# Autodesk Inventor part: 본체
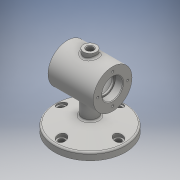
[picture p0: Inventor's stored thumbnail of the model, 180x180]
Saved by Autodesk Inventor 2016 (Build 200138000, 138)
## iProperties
Created: 2018-12
Part Number: 본체
Material: 일반
Document SubType Name: Modeling
Designer: 605-17
Density: 1 g/cm^3
Appearance: 기본값
Author: 605-17
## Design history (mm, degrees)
sketch "스케치1"
  geometry: C1 r 55 at (0, 0); 1 further point
  constraints: 1 centre point, 1 coincident
  dimensions: "d0" = 110 diameter of C1
extrude "돌출1" new body sketch "스케치1" distance "d1" = 11; taper "d2" = 0 deg
sketch "스케치2"
  geometry: L1 (0, 11)-(0, 22.522); L2 (0, 22.522)-(-12, 22.522); L3 (-12, 22.522)-(-55, 11); L4 (-55, 11)-(0, 11); L5 (-55, 0)-(-55, 11) reference; L6 (55, 11)-(-55, 11) reference; 2 further points
  constraints: 8 end point, 1 collinear, 1 midpoint, 1 perpendicular, 1 vertical, 1 vertical alignment
  dimensions: "d3" = 75 deg angle of L5 L3; "d4" = 12 distance of L2.end L1.end
revolve "회전1" sketch "스케치2" stored, may be unused: angle "d5" = 90 deg
sketch "스케치4"
  geometry: C1 r 30 at (0, 75); 1 further point
  constraints: 1 centre point, 1 vertical alignment
  dimensions: "d6" = 75 distance of point (0, 0) C1.centre; "d7" = 60 diameter of C1
extrude "돌출2" join sketch "스케치4" stored distance "d8" = 70; taper "d9" = 0 deg
sketch "스케치5"
  geometry: C1 r 12 at (0, 0); 1 further point
  constraints: 1 centre point, 1 coincident
  dimensions: "d10" = 24 diameter of C1
extrude "돌출3" join sketch "스케치5" stored distance "d11" = 70; taper "d12" = 0 deg; dims "d38" = 45 deg
sketch "스케치6"
  geometry: L1 (-35, 91)-(-23, 91); L2 (-23, 91)-(-23, 89); L3 (-23, 89)-(-20, 89); L4 (-20, 89)-(-20, 97); L5 (-17, 100)-(17, 100); L6 (20, 97)-(20, 89); L7 (20, 89)-(23, 89); L8 (23, 89)-(23, 91); L9 (23, 91)-(35, 91); L10 (35, 91)-(35, 75); L11 (35, 75)-(-35, 75); L12 (-35, 91)-(-35, 75); L13 (-35, 105)-(-35, 45) reference; A1 r 3 centre (-17, 97) between (-17, 100) and (-20, 97); A2 r 3 centre (17, 97) between (20, 97) and (17, 100); 3 further points
  constraints: 24 end point, 10 perpendicular, 6 point on line, 4 point on circle, 4 tangent, 2 centre point, 1 equal radius, 1 horizontal, 1 midpoint
  dimensions: "d13" = 16 distance of L1.start L11.end; "d14" = 14 distance from line of L11.end L3; "d15" = 12 distance of L1.start L1.end; "d16" = 3 distance of L2.end L3.end; "d17" = 16 distance from line of L10.end L9 (derived); "d18" = 14 distance from line of L10.end L7; "d19" = 3 distance of L6.end L7.end; "d20" = 12 distance of L8.end L9.end; "d21" = 40 distance of point (-20, 100) point (20, 100); "d22" = 25 distance from line of L10.end L5; "d24" = 3 radius of A1
revolve "회전2" sketch "스케치6" stored, may be unused: angle "d23" = 90 deg
chamfer "모따기1" distance "d25" = 1; stored, may be unused: second distance "d26" = 2, angle "d27" = 45 deg
node "작업 평면2"
sketch "스케치8"
  geometry: C1 r 10 at (0, 0); 1 further point
  constraints: 1 centre point, 1 coincident
  dimensions: "d29" = 20 diameter of C1
extrude "돌출4" join sketch "스케치8" stored distance "d30" = 70; taper "d31" = 0 deg; dims "d38" = 45 deg
sketch "스케치9"
  geometry: C1 r 5 at (0, 0); 1 further point
  constraints: 1 centre point, 1 coincident
  dimensions: "d32" = 10 diameter of C1
extrude "돌출5" cut sketch "스케치9" distance "d33" = 30; taper "d34" = 0 deg
fillet "모깎기1" dims "d35" = 0.3
chamfer "모따기2" distance "d36" = 1; stored, may be unused: second distance "d37" = 2, angle "d38" = 45 deg
sketch "스케치10"
  geometry: C1 r 30 at (0, 0) reference; A1 r 23 centre (0, 0) between (-23, 0) and (23, 0); 3 further points
  constraints: 4 point on circle, 2 horizontal alignment, 2 vertical alignment, 1 centre point, 1 coincident
  dimensions: "d39" = 46 diameter of A1
hole "구멍1" sketch "스케치10" at (-23, 0), (23, 0), (0, -23), (0, 23) diameter "d42" = 3.242; stored, may be unused: countersink angle "d46" = 90 deg, drill point angle "d48" = 118 deg; dims "d43" = 8, "d44" = 4, "d45" = 2, "d47" = 10
node "작업 평면3"
sketch "스케치11" dims "d49" = 88
  geometry: C1 r 4.5 at (0, 44); 2 further points
  constraints: 2 vertical alignment, 1 centre point, 1 coincident, 2 other
  dimensions: "d50" = 9 diameter of C1
extrude "돌출6" cut sketch "스케치11" distance "d51" = 10; taper "d52" = 0 deg
sketch "스케치12"
  geometry: C1 r 4.5 at (0, 0) reference; C2 r 7 at (0, 0); 1 further point
  constraints: 1 centre point, 1 coincident
  dimensions: "d53" = 14 diameter of C2
extrude "돌출7" cut sketch "스케치12" distance "d54" = 10; taper "d55" = 0 deg
fillet "모깎기2" dims "d59" = 3
fillet "모깎기3" dims "d60" = 3
node "작업 평면5"
sketch "스케치14"
  geometry: L1 (-35, 105)-(-35, 45) reference; L2 (35, 105)-(-35, 105) reference; 2 further points
  constraints: 1 other
  dimensions: "d63" = 35 distance from line of point (0, 75) L1; "d64" = 30 distance from line of point (0, 75) L2
feature "엠보싱1" sketch "스케치14" dims "d10" = 24, "d65" = 0.5, "d66" = 0
node "솔리드1"
mirror "대칭1"
pattern_circular "원형 패턴1" dims angle "d57" = 360 deg
other parameters: "d28" = 112, "d62" = 54.5
